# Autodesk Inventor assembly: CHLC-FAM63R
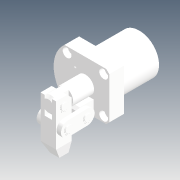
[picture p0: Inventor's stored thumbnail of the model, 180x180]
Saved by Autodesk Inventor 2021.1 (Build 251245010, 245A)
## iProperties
Created: 2019-04
Part Number: CHLC-FAM63R
Description: STEP AP214
Document SubType Name: Assembly
Designer: user
Title: CHLC-FAM63R.STEP
Revision Number: ÈÎºÎ
Sending System: SolidWorks 2016
Preprocessor: SwSTEP 2.0
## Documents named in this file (10)
- D:\Vault_2016\Projekty\Clamptek\Hydraulic\CHLC\CHLC-63\Inventor\CHLC-FAM63R\CHLC-FAM63R.iam
- D:\Vault_2016\Projekty\Clamptek\Hydraulic\CHLC\CHLC-63\Inventor\CHLC-FAM63R\benti.ipt
- D:\Vault_2016\Projekty\Clamptek\Hydraulic\CHLC\CHLC-63\Inventor\CHLC-FAM63R\CHLC-63-01.ipt
- D:\Vault_2016\Projekty\Clamptek\Hydraulic\CHLC\CHLC-63\Inventor\CHLC-FAM63R\CHLC-63-02.ipt
- D:\Vault_2016\Projekty\Clamptek\Hydraulic\CHLC\CHLC-63\Inventor\CHLC-FAM63R\CHLC-63-03.ipt
- D:\Vault_2016\Projekty\Clamptek\Hydraulic\CHLC\CHLC-63\Inventor\CHLC-FAM63R\CHLC-63-04.ipt
- D:\Vault_2016\Projekty\Clamptek\Hydraulic\CHLC\CHLC-63\Inventor\CHLC-FAM63R\CHLC-63-05.ipt
- D:\Vault_2016\Projekty\Clamptek\Hydraulic\CHLC\CHLC-63\Inventor\CHLC-FAM63R\CHLC-63-07.ipt
- D:\Vault_2016\Projekty\Clamptek\Hydraulic\CHLC\CHLC-63\Inventor\CHLC-FAM63R\socket set screw flat point_iso_ISO 4026 - M5 x 6-S.ipt
- D:\Vault_2016\Projekty\Clamptek\Hydraulic\CHLC\CHLC-63\Inventor\CHLC-FAM63R\YAKUAI.ipt
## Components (19 placed, 19 different names)
1. benti_1
2. CHLC-63-01_2
3. CHLC-63-02_3
4. CHLC-63-03_4
5. CHLC-63-04_5
6. CHLC-63-05_6
7. CHLC-63-07_7
8. socket set screw flat point_iso_ISO 4026 - M5 x 6-S_8
9. YAKUAI_9
10. CHLC-63-04_10
11. CHLC-63-07_11
12. CHLC-63-07_12
13. CHLC-63-07_13
14. CHLC-63-07_14
15. CHLC-63-07_15
16. CHLC-63-03_16
17. socket set screw flat point_iso_ISO 4026 - M5 x 6-S_17
18. socket set screw flat point_iso_ISO 4026 - M5 x 6-S_18
19. socket set screw flat point_iso_ISO 4026 - M5 x 6-S_19
